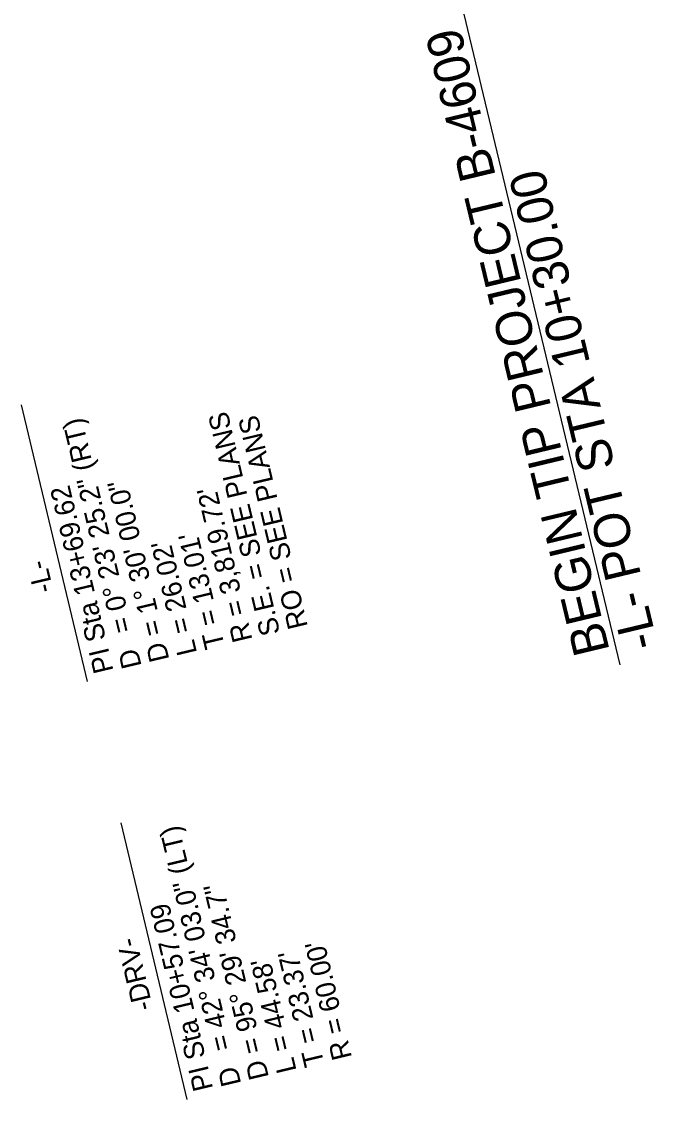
# Model space of a CAD drawing. Extents: x 1735795 to 1737428, y 699740 to 701024.
# Drawn here: x 1735811.1 to 1736033.1, y 699740.3 to 700118.9 of the extents above; entities that cross this region are included whole.
import ezdxf

# ---------------------------------------------------------------- set-up
doc = ezdxf.new("R2010")
doc.units = 0
for name, color, linetype in [('Prop DSN Text', 7, 'Continuous'), ('Prop Horizontal Alignment Curve and Spiral Data', 7, 'Continuous'), ('Prop Leader Line Heavy', 7, 'Continuous')]:
    doc.layers.add(name, color=color, linetype=linetype)

msp = doc.modelspace()

# ---------------------------------------------------------------- linework, layer by layer
at = {"layer": 'Prop Horizontal Alignment Curve and Spiral Data'}
for p, q in [((1735834.21, 699887.04), (1735811.05, 699984.22)), ((1735869.19, 699740.29), (1735846.03, 699837.46))]:
    msp.add_line(p, q, dxfattribs=at)
at = {"layer": 'Prop Leader Line Heavy'}
msp.add_line((1735960.42, 700146.42), (1736021.27, 699892.91), dxfattribs=at)

# ---------------------------------------------------------------- texts
at = {"layer": 'Prop DSN Text'}
for s, p in [('BEGIN TIP PROJECT B-4609', (1736017.73, 699897.92)), ('-L- POT STA 10+30.00', (1736034.69, 699899.75))]:
    msp.add_text(s, height=12.6, rotation=103.497, dxfattribs=at).set_placement(p)
at = {"layer": 'Prop Horizontal Alignment Curve and Spiral Data'}
for s, rotation, p in [('S.E. = SEE PLANS', 103.3793, (1735901.93, 699904.11)), ('= 0%%d 23\' 25.2" (RT)', 103.3793, (1735850.02, 699904.97)), ('RO = SEE PLANS', 103.3793, (1735911.66, 699906.42)), ('PI Sta 13+69.62', 103.3793, (1735843.4, 699890.88)), ('D = 1%%d 30\' 00.0"', 103.3793, (1735863.01, 699894.85)), ("R = 3,819.72'", 103.3793, (1735892.2, 699901.8)), ("L = 26.02'", 103.3793, (1735872.74, 699897.17)), ("T = 13.01'", 103.3793, (1735882.47, 699899.48)), ('-L-', 103.3793, (1735822.29, 699919.07)), ('D', 103.3793, (1735853.28, 699892.54)), ('= 42%%d 34\' 03.0" (LT)', 103.4059, (1735884.99, 699758.22)), ('D = 95%%d 29\' 34.7"', 103.4059, (1735897.99, 699748.11)), ('PI Sta 10+57.09', 103.4059, (1735878.38, 699744.13)), ('-DRV-', 103.3793, (1735857.27, 699772.31)), ("T = 23.37'", 103.4059, (1735917.44, 699752.74)), ("R = 60.00'", 103.4059, (1735927.17, 699755.06)), ("L = 44.58'", 103.4059, (1735907.72, 699750.43)), ('D', 103.4059, (1735888.26, 699745.79))]:
    msp.add_text(s, height=7, rotation=rotation, dxfattribs=at).set_placement(p)

doc.saveas('drawing.dxf')
